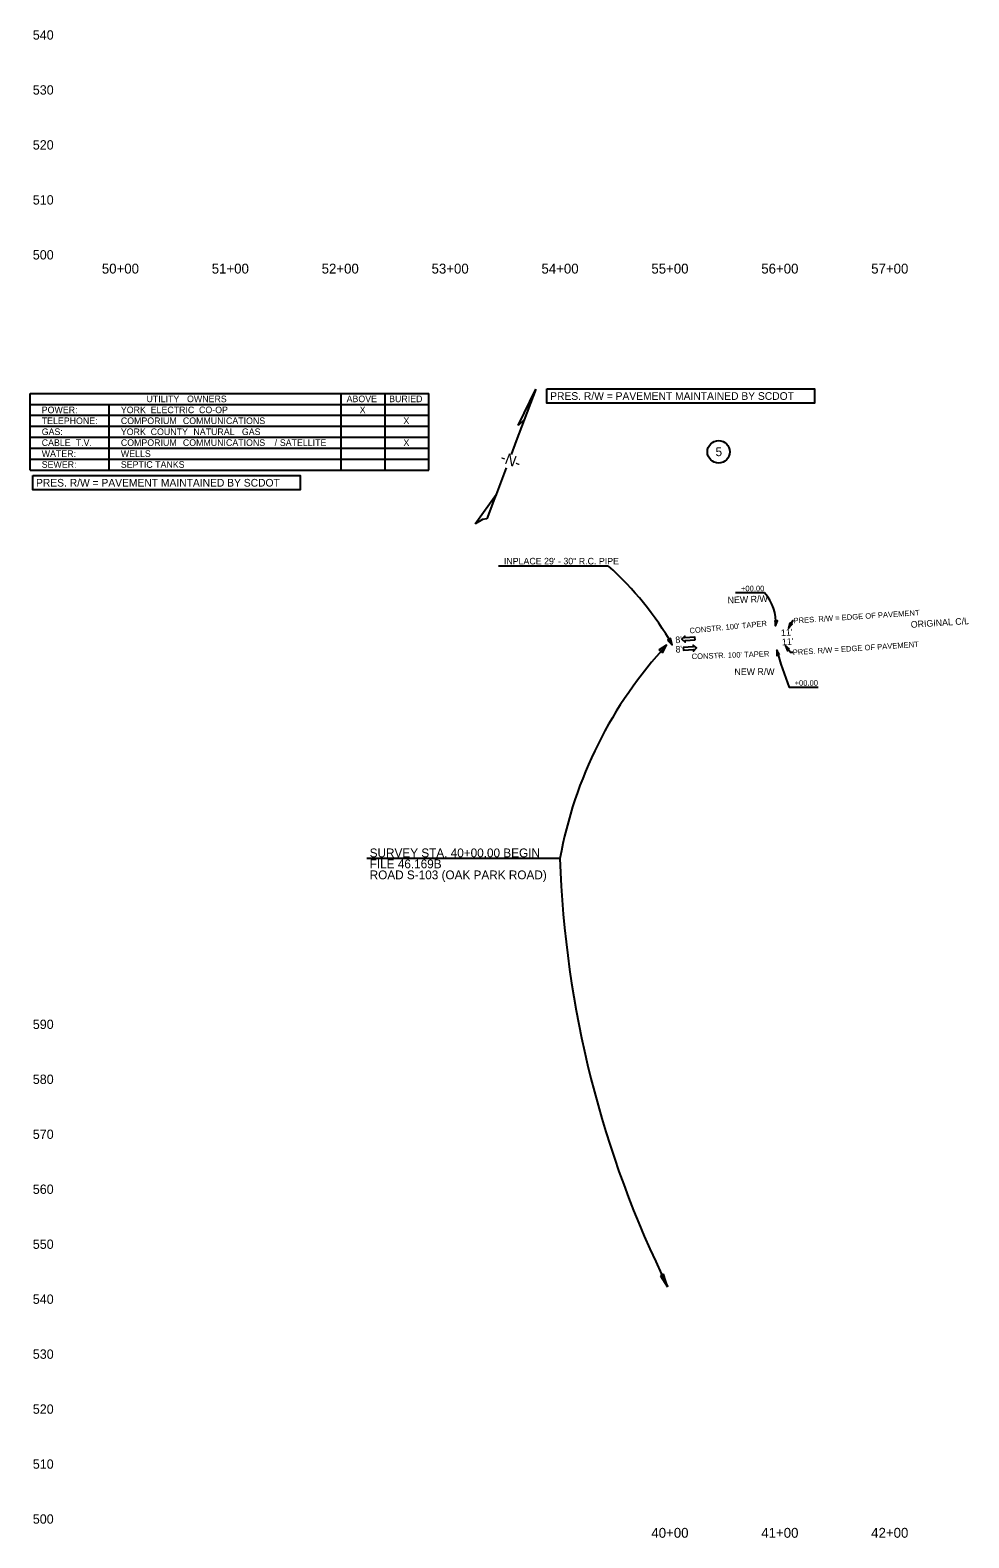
# Model space of a CAD drawing. Extents: x 1964377 to 1966966, y 1116414 to 1123213.
# Drawn here: x 1965291 to 1966145, y 1116414 to 1117785 of the extents above; entities that cross this region are included whole.
import ezdxf

# ---------------------------------------------------------------- set-up
doc = ezdxf.new("R2010")
doc.units = 0
for name, color, linetype in [('RD_DDB_Profile_Elev', 7, 'Continuous'), ('RD_DDB_StaTX', 7, 'Continuous'), ('RD_EX_DV_TX_Prop', 7, 'Continuous'), ('RD_EX_Misc', 7, 'Continuous'), ('RD_EX_RW_TX', 7, 'Continuous'), ('RD_PD_Final_LnLine', 7, 'Continuous'), ('RD_PD_Final_TX', 7, 'Continuous'), ('RD_PD_RW_TX', 7, 'Continuous'), ('RD_TX_Drainage', 7, 'Continuous'), ('RD_TX_Misc1', 7, 'Continuous'), ('RD_TX_RoadID', 7, 'Continuous'), ('RD_TX_StaOff', 7, 'Continuous')]:
    doc.layers.add(name, color=color, linetype=linetype)

msp = doc.modelspace()

# ---------------------------------------------------------------- linework, layer by layer
at = {"layer": 'RD_EX_DV_TX_Prop'}
msp.add_circle((1965917.8, 1117401.8), 10.2, dxfattribs=at)
at = {"layer": 'RD_EX_Misc'}
for p, q in [((1965735.5, 1117425.8), (1965751.4, 1117458.7)), ((1965751.4, 1117458.7), (1965741, 1117431)), ((1965741, 1117431), (1965733.7, 1117411.8)), ((1965741, 1117431), (1965735.5, 1117425.8)), ((1965733.7, 1117411.8), (1965729.1, 1117399.5)), ((1965724.5, 1117387.3), (1965715.3, 1117363)), ((1965696.4, 1117336.2), (1965715.3, 1117363)), ((1965714, 1117359.4), (1965707, 1117340.8)), ((1965715.3, 1117363), (1965714, 1117359.4))]:
    msp.add_line(p, q, dxfattribs=at)
msp.add_lwpolyline([(1965707, 1117340.8), (1965703, 1117340.2), (1965696.4, 1117336.2)], dxfattribs=at)
at = {"layer": 'RD_EX_RW_TX'}
for points in [[(1965761.5, 1117459.1), (1966004.9, 1117459.1), (1966004.9, 1117446.1), (1965761.5, 1117446.1)], [(1965293.7, 1117380.2), (1965537.1, 1117380.2), (1965537.1, 1117367.2), (1965293.7, 1117367.2)], [(1965982.5, 1117246.3), (1965981.3, 1117241.4), (1965984.8, 1117245.1)], [(1965982.4, 1117222.3), (1965978.5, 1117225.4), (1965980.4, 1117220.7)]]:
    msp.add_lwpolyline(points, close=True, dxfattribs=at)
for points in [[(1965986, 1117248.2), (1965984.9, 1117248.1), (1965981.3, 1117241.4)], [(1965985.3, 1117219.4), (1965983.1, 1117219.2), (1965978.5, 1117225.4)]]:
    msp.add_lwpolyline(points, dxfattribs=at)
at = {"layer": 'RD_PD_Final_LnLine'}
for points in [[(1965896.4, 1117230.9), (1965896.2, 1117233.3), (1965887.1, 1117232.7), (1965887, 1117234.3), (1965884.3, 1117231.3), (1965887.3, 1117228.6), (1965887.2, 1117230.3)], [(1965885.5, 1117223.9), (1965885.7, 1117221.5), (1965894.8, 1117222.1), (1965894.9, 1117220.5), (1965897.6, 1117223.5), (1965894.6, 1117226.1), (1965894.7, 1117224.5)]]:
    msp.add_lwpolyline(points, close=True, dxfattribs=at)
at = {"layer": 'RD_PD_Final_TX'}
for p, q in [((1965959.5, 1117273.6), (1965933.2, 1117273.5)), ((1966008.4, 1117187.6), (1965982.1, 1117187.6)), ((1965773.4, 1117032), (1965597.8, 1117032)), ((1965867.5, 1116653.8), (1965864.8, 1116652.4)), ((1965864.8, 1116652.4), (1965871.4, 1116642.4)), ((1965871.4, 1116642.4), (1965867.5, 1116653.8))]:
    msp.add_line(p, q, dxfattribs=at)
for points in [[(1965968.8, 1117248.4), (1965969.5, 1117243.4), (1965971.3, 1117248.1)], [(1965866.7, 1117218.9), (1965870.4, 1117226), (1965863.6, 1117221.7)], [(1965973.3, 1117217.1), (1965970.9, 1117221.5), (1965970.8, 1117216.5)]]:
    msp.add_lwpolyline(points, close=True, dxfattribs=at)
for centre, radius, start, end in [((1965932.3, 1117247.8), 37.4, 353.2618, 43.4618), ((1966154, 1116962.9), 386.8, 137.1475, 169.7086), ((1966217.8, 1117284), 254.7, 194.2085, 202.2537), ((1966721.3, 1117063.4), 948.4, 181.8978, 206.3563)]:
    msp.add_arc(centre, radius, start, end, dxfattribs=at)
at = {"layer": 'RD_TX_Drainage'}
msp.add_line((1965817.4, 1117297.9), (1965717.4, 1117297.9), dxfattribs=at)
msp.add_lwpolyline([(1965871.3, 1117230.5), (1965875.6, 1117226.3), (1965874, 1117232.1)], close=True, dxfattribs=at)
msp.add_arc((1965623.8, 1117081.3), 290.6, 29.9361, 48.2041, dxfattribs=at)
at = {"layer": 'RD_TX_Misc1'}
for p, q in [((1965291.4, 1117454.9), (1965654.1, 1117454.9)), ((1965291.4, 1117385.3), (1965291.4, 1117454.9)), ((1965574.5, 1117385.3), (1965574.5, 1117454.9)), ((1965614.3, 1117385.3), (1965614.3, 1117454.9)), ((1965654.1, 1117385.3), (1965654.1, 1117454.9)), ((1965291.4, 1117445), (1965654.1, 1117445)), ((1965291.4, 1117435.1), (1965654.1, 1117435.1)), ((1965363.3, 1117385.3), (1965363.3, 1117445)), ((1965291.4, 1117425.1), (1965654.1, 1117425.1)), ((1965291.4, 1117415.2), (1965654.1, 1117415.2)), ((1965291.4, 1117405.2), (1965654.1, 1117405.2)), ((1965291.4, 1117395.3), (1965654.1, 1117395.3)), ((1965291.4, 1117385.3), (1965654.1, 1117385.3))]:
    msp.add_line(p, q, dxfattribs=at)
at = {"layer": 'RD_TX_StaOff'}
msp.add_line((1965291.4, 1117454.9), (1965291.4, 1117454.9), dxfattribs=at)

# ---------------------------------------------------------------- texts
at = {"layer": 'RD_DDB_Profile_Elev'}
for s, p in [('540', (1965293.8, 1117776.8)), ('530', (1965293.8, 1117726.8)), ('520', (1965293.8, 1117676.8)), ('510', (1965293.8, 1117626.8)), ('500', (1965293.8, 1117576.8)), ('590', (1965293.8, 1116876.8)), ('580', (1965293.8, 1116826.8)), ('570', (1965293.8, 1116776.8)), ('560', (1965293.8, 1116726.8)), ('550', (1965293.8, 1116676.8)), ('540', (1965293.8, 1116626.8)), ('530', (1965293.8, 1116576.8)), ('520', (1965293.8, 1116526.8)), ('510', (1965293.8, 1116476.8)), ('500', (1965293.8, 1116426.8))]:
    msp.add_text(s, height=8.5, dxfattribs=at).set_placement(p)
at = {"layer": 'RD_DDB_StaTX'}
for s, p in [('50+00', (1965356.6, 1117564)), ('51+00', (1965456.6, 1117564)), ('52+00', (1965556.6, 1117564)), ('53+00', (1965656.6, 1117564)), ('54+00', (1965756.6, 1117564)), ('55+00', (1965856.6, 1117564)), ('56+00', (1965956.6, 1117564)), ('57+00', (1966056.6, 1117564)), ('40+00', (1965856.6, 1116414)), ('41+00', (1965956.6, 1116414)), ('42+00', (1966056.6, 1116414))]:
    msp.add_text(s, height=9, dxfattribs=at).set_placement(p)
at = {"layer": 'RD_EX_DV_TX_Prop'}
msp.add_text('5', height=8, dxfattribs=at).set_placement((1965915, 1117397.9))
at = {"layer": 'RD_EX_Misc'}
msp.add_text('-N-', height=10, rotation=339.3369, dxfattribs=at).set_placement((1965718.3, 1117393))
at = {"layer": 'RD_EX_RW_TX'}
for p in [(1965764.5, 1117449.1), (1965296.7, 1117370.2)]:
    msp.add_text('PRES. R/W = PAVEMENT MAINTAINED BY SCDOT', height=7, dxfattribs=at).set_placement(p)
for p in [(1965986.1, 1117245.7), (1965985.4, 1117216.9)]:
    msp.add_text('PRES. R/W = EDGE OF PAVEMENT', height=5, rotation=3.7195, dxfattribs=at).set_placement(p)
at = {"layer": 'RD_PD_Final_TX'}
for s, height, rotation, p in [('+00.00', 5, 0.1723, (1965938.1, 1117275)), ("CONSTR. 100' TAPER", 5, 5.4948, (1965891.5, 1117236.6)), ("8'", 6, 3.7195, (1965878.6, 1117227.7)), ("11'", 6, 3.7195, (1965974.7, 1117234.2)), ("11'", 6, 3.7195, (1965975.6, 1117225.8)), ("8'", 6, 3.7195, (1965878.8, 1117219.1)), ("CONSTR. 100' TAPER", 5, 2.0257, (1965893.3, 1117213.2)), ('+00.00', 5, 0.1723, (1965986.9, 1117189.1))]:
    msp.add_text(s, height=height, rotation=rotation, dxfattribs=at).set_placement(p)
for s, p in [('SURVEY STA. 40+00.00 BEGIN', (1965600.3, 1117033)), ('FILE 46.169B', (1965600.3, 1117023)), ('ROAD S-103 (OAK PARK ROAD)', (1965600.3, 1117013))]:
    msp.add_text(s, height=8, dxfattribs=at).set_placement(p)
at = {"layer": 'RD_PD_RW_TX'}
for rotation, p in [(2.3164, (1965926.1, 1117263.9)), (0.4538, (1965932.2, 1117198.7))]:
    msp.add_text('NEW R/W', height=6, rotation=rotation, dxfattribs=at).set_placement(p)
at = {"layer": 'RD_TX_Drainage'}
msp.add_text('INPLACE 29\' - 30" R.C. PIPE', height=6, dxfattribs=at).set_placement((1965722.4, 1117299.4))
at = {"layer": 'RD_TX_Misc1'}
for s, p in [(' UTILITY', (1965395, 1117447)), (' OWNERS', (1965431.9, 1117447)), ('ABOVE', (1965579.3, 1117447)), ('BURIED', (1965618, 1117447)), ('POWER:', (1965301.9, 1117437)), ('YORK', (1965373.9, 1117437)), (' ELECTRIC', (1965398.8, 1117437)), (' CO-OP', (1965442.8, 1117437)), ('X', (1965591.2, 1117437)), ('TELEPHONE:', (1965301.9, 1117427.1)), ('GAS:', (1965301.9, 1117417.1)), ('YORK', (1965373.9, 1117417.1)), ('COMPORIUM', (1965373.9, 1117427.1)), (' COUNTY', (1965398.8, 1117417.1)), (' COMMUNICATIONS', (1965428.1, 1117427.1)), (' NATURAL', (1965437.7, 1117417.1)), (' GAS', (1965481.8, 1117417.1)), ('X', (1965631, 1117427.1)), ('CABLE', (1965301.9, 1117407.2)), (' T.V.', (1965330.6, 1117407.2)), ('COMPORIUM', (1965373.9, 1117407.2)), (' COMMUNICATIONS', (1965428.1, 1117407.2)), (' /', (1965511.6, 1117407.2)), (' SATELLITE', (1965516.3, 1117407.2)), ('X', (1965631, 1117407.2)), ('WATER:', (1965301.9, 1117397.2)), ('SEWER:', (1965301.9, 1117387.3)), ('WELLS', (1965373.9, 1117397.2)), ('SEPTIC', (1965373.9, 1117387.3)), (' TANKS', (1965402.9, 1117387.3))]:
    msp.add_text(s, height=6, dxfattribs=at).set_placement(p)
at = {"layer": 'RD_TX_RoadID'}
msp.add_text('ORIGINAL C/L', height=6, rotation=3.7195, dxfattribs=at).set_placement((1966092.8, 1117241.7))

doc.saveas('drawing.dxf')
